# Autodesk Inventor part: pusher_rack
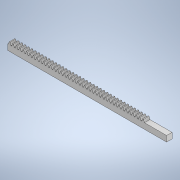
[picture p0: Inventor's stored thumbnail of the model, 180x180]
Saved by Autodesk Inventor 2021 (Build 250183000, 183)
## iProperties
Company: meta-matic.com
Created: 2026-10
Part Number: pusher_rack
Material: Generic
Description: Rack Gear - meta-matic-generator 1.3
Document SubType Name: Modeling
Designer: alolo
Authority: META-MATIC-ID: 956ca585bc87
Density: 1 g/cm^3
Appearance: Default
Sending System: Open CASCADE
Preprocessor: meta-matic-generator 1.3
Title: Rack Gear_956ca585bc87
Author: Takahashi Mizuki @tkhsmz
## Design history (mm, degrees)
feature "Base1"
sketch "Sketch1"
  geometry: L1 (0, 10.5)-(0, 0) reference; L2 (10, 0)-(0, 0); L3 (0, 0)-(0, 10.5); L4 (0, 10.5)-(10, 10.5); L5 (10, 10.5)-(10, 0); 1 further point
  constraints: 8 end point, 2 parallel, 1 horizontal, 1 perpendicular
extrude "Extrusion1" join sketch "Sketch1" distance "d0" = 40; taper "d1" = 0 deg
body "Solid1"
